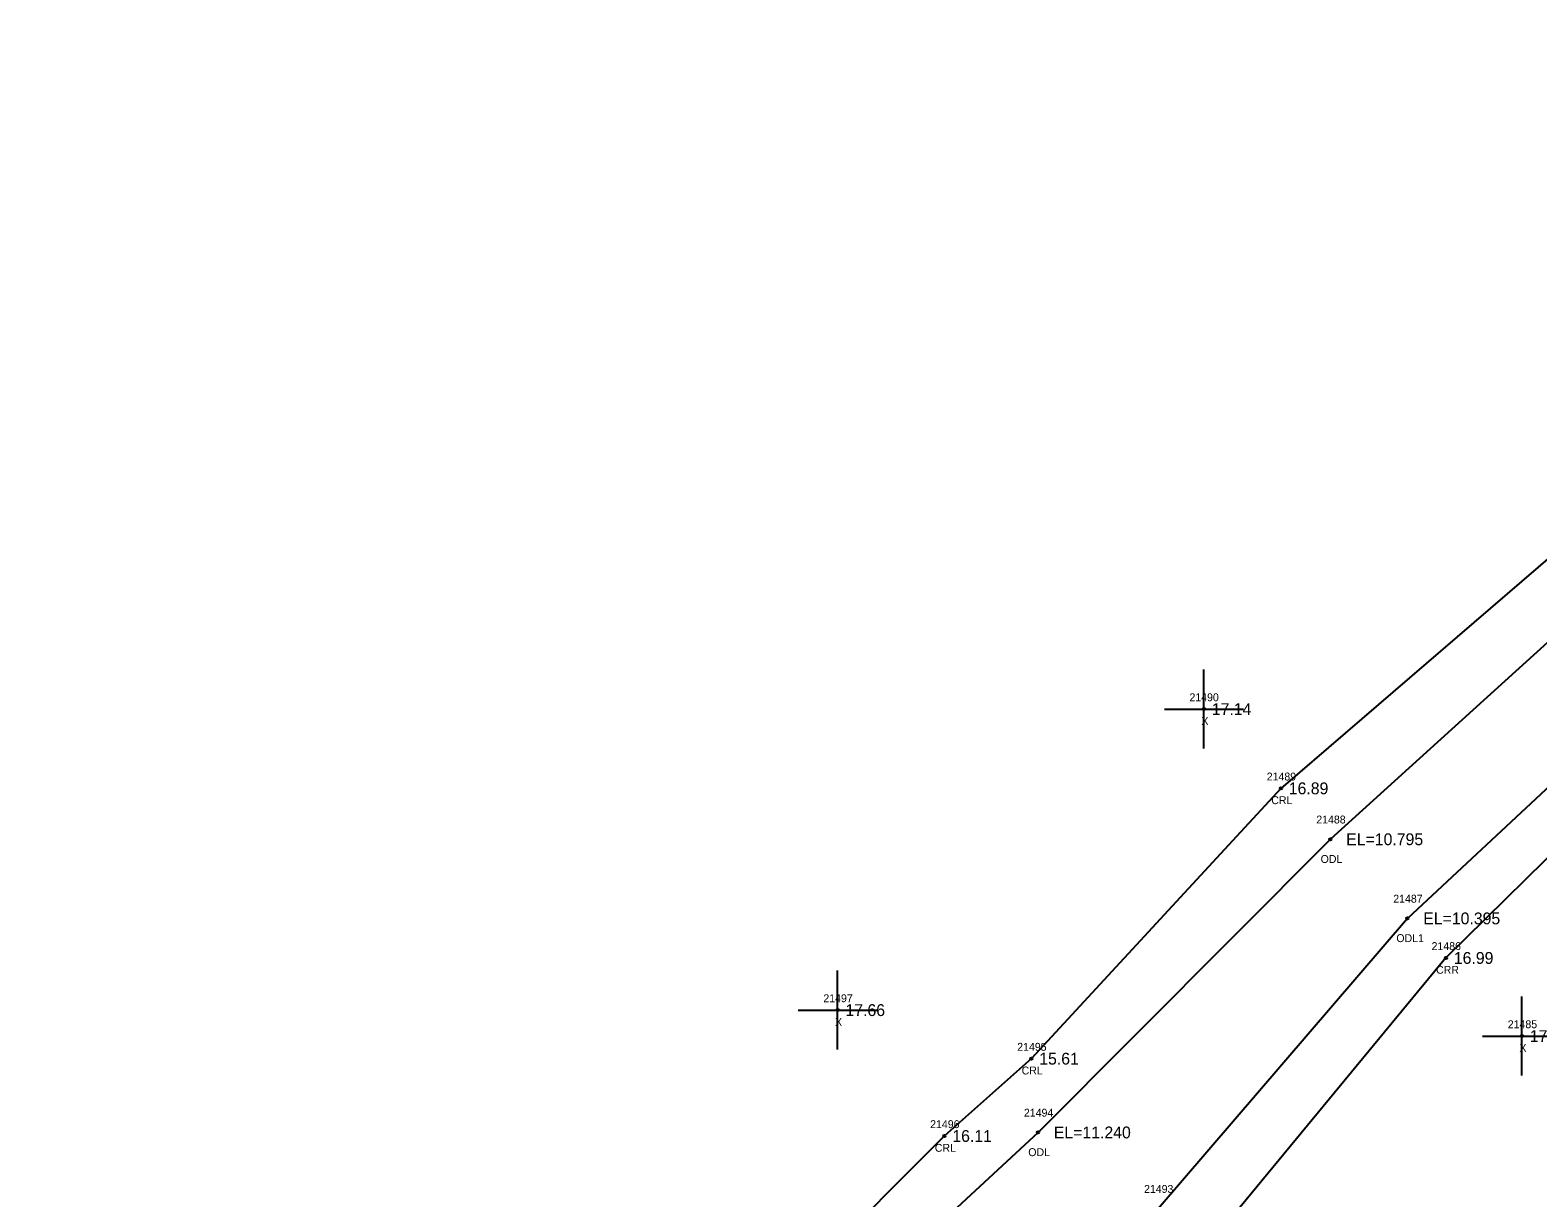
# Model space of a CAD drawing. Extents: x 2655177 to 2656219, y 761780 to 764748.
# Drawn here: x 2655287.7 to 2655478.9, y 763103.7 to 763251.6 of the extents above; entities that cross this region are included whole.
import ezdxf

# ---------------------------------------------------------------- set-up
doc = ezdxf.new("R2010")
doc.units = 0
for name, color, linetype in [('RD_EX_H2O', 7, 'Continuous'), ('RD_EX_H2O_txCode', 7, 'Continuous'), ('RD_EX_Misc', 7, 'Continuous'), ('RD_EX_Misc_txCode', 7, 'Continuous'), ('RD_EX_TX_H2O_ELEV', 7, 'Continuous'), ('RD_EX_TX_Misc_ELEV', 7, 'Continuous'), ('RD_SMD_Locator', 7, 'Continuous')]:
    doc.layers.add(name, color=color, linetype=linetype)

msp = doc.modelspace()

# ---------------------------------------------------------------- linework, layer by layer
at = {"layer": 'RD_EX_H2O'}
for points in [[(2655679.52, 763275.1), (2655669.12, 763275.51), (2655637.94, 763272.95), (2655565.65, 763249.44), (2655503.41, 763204.6), (2655446.32, 763155.55), (2655414.68, 763121.3), (2655403.66, 763111.5), (2655354.39, 763062.15), (2655287.73, 762993.08)], [(2655756.39, 763249.8), (2655684.92, 763267.82), (2655683.42, 763267.23), (2655668.47, 763267.53), (2655668.47, 763267.53), (2655638.16, 763264.95), (2655569.96, 763242.71), (2655508.09, 763199.39), (2655452.6, 763149.1), (2655415.53, 763111.95), (2655357.86, 763058.55), (2655292.21, 762987.7)], [(2655752.5, 763238.32), (2655667.49, 763255.57), (2655638.64, 763247.96), (2655576.44, 763232.61), (2655516.78, 763189.73), (2655462.37, 763139.07), (2655430.77, 763102.29), (2655369.67, 763046.31), (2655300.53, 762977.71)], [(2655730.43, 763238.59), (2655686.81, 763240.78), (2655666.68, 763245.61), (2655638.83, 763240.96), (2655580.22, 763226.71), (2655520.12, 763186.01), (2655467.25, 763134.06), (2655436.95, 763097.37), (2655374.53, 763041.27), (2655306.29, 762970.79)]]:
    msp.add_lwpolyline(points, dxfattribs=at)
at = {"layer": 'RD_EX_Misc'}
for p, q in [((2655436.56, 763160.59), (2655436.56, 763170.59)), ((2655431.56, 763165.59), (2655441.56, 763165.59)), ((2655390.11, 763122.45), (2655390.11, 763132.45)), ((2655476.88, 763119.16), (2655476.88, 763129.16)), ((2655385.11, 763127.45), (2655395.11, 763127.45)), ((2655471.88, 763124.16), (2655481.88, 763124.16))]:
    msp.add_line(p, q, dxfattribs=at)
at = {"layer": 'RD_SMD_Locator'}
for centre in [(2655436.56, 763165.59), (2655446.32, 763155.55), (2655452.6, 763149.1), (2655462.37, 763139.07), (2655467.25, 763134.06), (2655390.11, 763127.45), (2655476.88, 763124.16), (2655414.68, 763121.3), (2655403.66, 763111.5), (2655415.53, 763111.95)]:
    msp.add_circle(centre, 0.15, dxfattribs=at)

# ---------------------------------------------------------------- texts
at = {"layer": 'RD_EX_H2O_txCode'}
for s, p in [('21489', (2655444.53, 763156.55)), ('CRL', (2655445.1, 763153.55)), ('21488', (2655450.81, 763151.1)), ('ODL', (2655451.36, 763146.1)), ('21487', (2655460.57, 763141.07)), ('ODL1', (2655460.96, 763136.07)), ('21486', (2655465.43, 763135.06)), ('CRR', (2655466, 763132.06)), ('21495', (2655412.89, 763122.3)), ('CRL', (2655413.45, 763119.3)), ('21496', (2655401.85, 763112.5)), ('21494', (2655413.74, 763113.95)), ('CRL', (2655402.44, 763109.5)), ('ODL', (2655414.29, 763108.95)), ('21493', (2655428.97, 763104.29))]:
    msp.add_text(s, height=1, dxfattribs=at).set_placement(p)
at = {"layer": 'RD_EX_Misc_txCode'}
for s, p in [('21490', (2655434.73, 763166.59)), ('X', (2655436.24, 763163.59)), ('21497', (2655388.31, 763128.45)), ('X', (2655389.79, 763125.45)), ('21485', (2655475.09, 763125.16)), ('X', (2655476.57, 763122.16))]:
    msp.add_text(s, height=1, dxfattribs=at).set_placement(p)
at = {"layer": 'RD_EX_TX_H2O_ELEV'}
for s, p in [('16.89', (2655447.32, 763154.8)), ('EL=10.795', (2655454.6, 763148.35)), ('EL=10.395', (2655464.37, 763138.32)), ('16.99', (2655468.25, 763133.31)), ('15.61', (2655415.68, 763120.55)), ('16.11', (2655404.66, 763110.75)), ('EL=11.240', (2655417.53, 763111.2))]:
    msp.add_text(s, height=1.5, dxfattribs=at).set_placement(p)
at = {"layer": 'RD_EX_TX_Misc_ELEV'}
for s, p in [('17.14', (2655437.56, 763164.84)), ('17.66', (2655391.11, 763126.7)), ('17.36', (2655477.88, 763123.41))]:
    msp.add_text(s, height=1.5, dxfattribs=at).set_placement(p)

doc.saveas('drawing.dxf')
